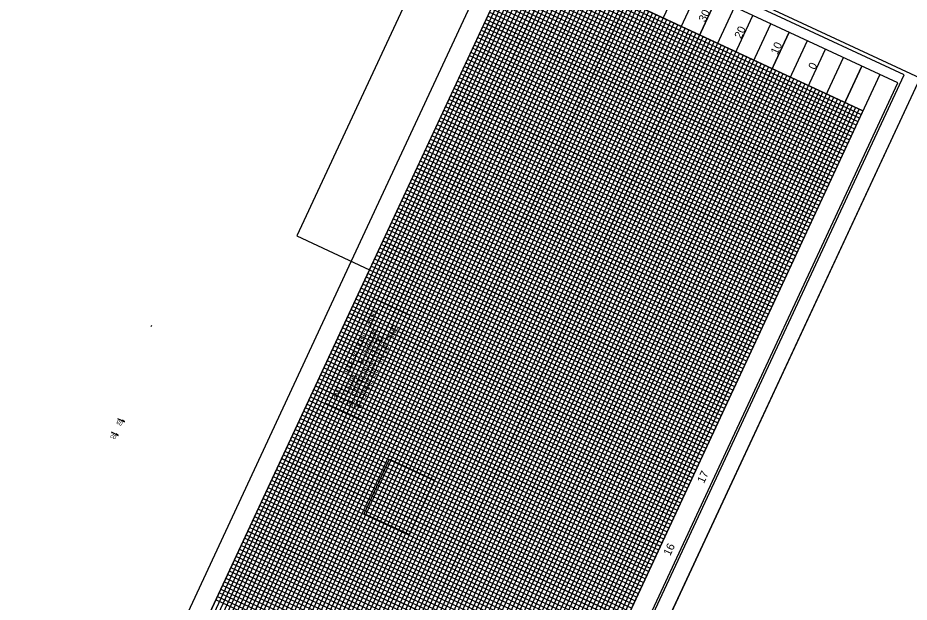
# Model space of a CAD drawing. Extents: x 2532214 to 2534758, y 714172 to 717266.
# Drawn here: x 2532790 to 2533904, y 715503 to 716233 of the extents above; entities that cross this region are included whole.
import ezdxf

# ---------------------------------------------------------------- set-up
doc = ezdxf.new("R2010")
doc.units = 0
for name, color, linetype in [('Arrowhead Terminators', 7, 'Continuous'), ('Default', 7, 'Continuous'), ('Dimension Lines', 7, 'Continuous'), ('Dimension Lines CELL', 7, 'Continuous'), ('Enter Data Field Text', 7, 'Continuous'), ('Mis Existing Structures', 7, 'Continuous'), ('Mis Ground Lines', 7, 'Continuous'), ('Plan Sheet', 7, 'Continuous'), ('Rebar Hooks Both Ends', 7, 'Continuous'), ('Rebar Lines', 7, 'Continuous'), ('Rebar with Hook on Left End', 7, 'Continuous'), ('Structural Steel Angle 3 x 3', 7, 'Continuous'), ('Structural Steel Channel 12', 7, 'Continuous'), ('Structural Steel Lines', 7, 'Continuous'), ('Subtitle Text', 7, 'Continuous'), ('Sup Concrete Girder Lines', 7, 'Continuous')]:
    doc.layers.add(name, color=color, linetype=linetype)

msp = doc.modelspace()

# ---------------------------------------------------------------- linework, layer by layer
at = {"layer": 'Arrowhead Terminators'}
msp.add_line((2533206.9, 714631.3), (2533917.1, 716157.7), dxfattribs=at)
at = {"layer": 'Default'}
for points in [[(2533174.3, 715751.9), (2533235, 715882.3), (2533280.2, 715861.3), (2533219.5, 715730.8)], [(2533174.3, 715751.9), (2533235, 715882.3), (2533280.2, 715861.3), (2533219.5, 715730.8)], [(2533223, 715613.7), (2533254.6, 715681.7), (2533310.6, 715655.7), (2533279, 715587.7)], [(2533223, 715613.7), (2533254.6, 715681.7), (2533310.6, 715655.7), (2533279, 715587.7)]]:
    msp.add_lwpolyline(points, close=True, dxfattribs=at)
at = {"layer": 'Dimension Lines'}
for p, q in [((2532826.1, 714992.1), (2533458.9, 716352.2)), ((2533504.2, 716331.1), (2532871.4, 714971.1)), ((2532916.8, 714950), (2533549.5, 716310)), ((2533404.5, 716294.7), (2533835.2, 716094.3)), ((2533594.9, 716288.9), (2532962.1, 714928.9)), ((2533007.4, 714907.8), (2533640.2, 716267.8)), ((2533814.1, 716049), (2533383.5, 716249.4)), ((2533685.5, 716246.7), (2533052.8, 714886.7)), ((2533098.1, 714865.6), (2533730.9, 716225.6)), ((2533776.2, 716204.5), (2533143.4, 714844.5)), ((2533362.4, 716204), (2533793, 716003.7)), ((2533188.8, 714823.4), (2533821.5, 716183.4)), ((2533771.9, 715958.3), (2533341.3, 716158.7)), ((2533320.2, 716113.4), (2533750.9, 715913)), ((2533729.8, 715867.7), (2533299.1, 716068)), ((2533278, 716022.7), (2533708.7, 715822.3)), ((2533687.6, 715777), (2533256.9, 715977.4)), ((2533235.8, 715932), (2533666.5, 715731.7)), ((2533645.4, 715686.3), (2533214.7, 715886.7)), ((2533193.6, 715841.4), (2533624.3, 715641)), ((2533603.2, 715595.7), (2533172.5, 715796)), ((2533151.5, 715750.7), (2533582.1, 715550.3)), ((2533561, 715505), (2533130.4, 715705.4)), ((2533109.3, 715660), (2533539.9, 715459.7)), ((2533518.8, 715414.3), (2533088.2, 715614.7)), ((2533067.1, 715569.4), (2533497.8, 715369)), ((2533476.7, 715323.7), (2533046, 715524))]:
    msp.add_line(p, q, dxfattribs=at)
at = {"layer": 'Dimension Lines CELL'}
msp.add_lwpolyline([(2533392.4, 716327.9), (2533206.8, 715929), (2532801.9, 715058.6), (2532325.9, 715280), (2532853.1, 716413.3), (2533042.4, 716325.3), (2533105.7, 716461.3), (2533324.4, 716359.6)], close=True, dxfattribs=at)
at = {"layer": 'Enter Data Field Text'}
msp.add_line((2532957.3, 715848.8), (2532956.5, 715847.2), dxfattribs=at)
for points in [[(2532923.4, 715728.3), (2532921.2, 715730.5), (2532921.3, 715729.3)], [(2532915.5, 715711.4), (2532913.3, 715713.6), (2532913.5, 715712.4)]]:
    msp.add_lwpolyline(points, close=True, dxfattribs=at)
at = {"layer": 'Mis Existing Structures'}
msp.add_lwpolyline([(2533194.3, 714651.5), (2533897.1, 716162.1), (2532940.5, 716607.1), (2532237.8, 715096.6)], close=True, dxfattribs=at)
at = {"layer": 'Mis Ground Lines'}
msp.add_lwpolyline([(2533206.9, 714631.3), (2533917.1, 716157.7), (2532924.3, 716619.6), (2532214.1, 715093.2)], close=True, dxfattribs=at)
at = {"layer": 'Plan Sheet'}
for p, q in [((2532848.8, 714981.6), (2533460.4, 716296.3)), ((2532939.4, 714939.4), (2533572.2, 716299.4)), ((2532894.1, 714960.5), (2533505.8, 716275.2)), ((2532984.8, 714918.3), (2533617.5, 716278.3)), ((2533394, 716272), (2533824.7, 716071.7)), ((2533030.1, 714897.2), (2533662.9, 716257.2)), ((2533075.4, 714876.1), (2533708.2, 716236.2)), ((2533372.9, 716226.7), (2533803.6, 716026.3)), ((2533120.8, 714855), (2533753.5, 716215.1)), ((2533166.1, 714834), (2533798.9, 716194)), ((2533351.8, 716181.4), (2533782.5, 715981)), ((2533211.4, 714812.9), (2533844.2, 716172.9)), ((2533330.7, 716136), (2533761.4, 715935.7)), ((2533309.6, 716090.7), (2533740.3, 715890.3)), ((2533288.5, 716045.4), (2533719.2, 715845)), ((2533267.5, 716000), (2533698.1, 715799.7)), ((2533246.4, 715954.7), (2533677, 715754.3)), ((2533225.3, 715909.4), (2533655.9, 715709)), ((2533204.2, 715864), (2533634.8, 715663.7)), ((2533183.1, 715818.7), (2533613.8, 715618.3)), ((2533162, 715773.4), (2533592.7, 715573)), ((2533140.9, 715728), (2533571.6, 715527.7)), ((2533119.8, 715682.7), (2533550.5, 715482.3)), ((2533098.7, 715637.4), (2533529.4, 715437)), ((2533077.6, 715592), (2533508.3, 715391.7)), ((2533056.5, 715546.7), (2533487.2, 715346.3))]:
    msp.add_line(p, q, dxfattribs=at)
at = {"layer": 'Rebar Lines'}
for p, q in [((2533419.6, 716315.3), (2532829.1, 715045.9)), ((2532833.6, 715043.8), (2533424.2, 716313.2)), ((2533428.7, 716311), (2532838.1, 715041.7)), ((2532842.7, 715039.6), (2533433.2, 716308.9)), ((2533442.3, 716304.7), (2532851.7, 715035.4)), ((2533408.8, 716303.8), (2533839.4, 716103.4)), ((2533841.5, 716107.9), (2533410.9, 716308.3)), ((2533413, 716312.8), (2533843.7, 716112.5)), ((2532856.3, 715033.3), (2533446.8, 716302.6)), ((2533451.4, 716300.5), (2532860.8, 715031.1)), ((2532865.3, 715029), (2533455.9, 716298.4)), ((2533465, 716294.2), (2532874.4, 715024.8)), ((2533837.3, 716098.9), (2533406.7, 716299.2)), ((2532878.9, 715022.7), (2533469.5, 716292.1)), ((2533474, 716289.9), (2532883.5, 715020.6)), ((2532888, 715018.5), (2533478.6, 716287.8)), ((2533487.6, 716283.6), (2532897.1, 715014.3)), ((2532901.6, 715012.2), (2533492.2, 716281.5)), ((2533831, 716085.3), (2533400.3, 716285.6)), ((2533402.4, 716290.2), (2533833.1, 716089.8)), ((2533496.7, 716279.4), (2532906.1, 715010.1)), ((2532910.7, 715007.9), (2533501.2, 716277.3)), ((2532919.7, 715003.7), (2533510.3, 716273.1)), ((2533514.8, 716271), (2532924.3, 715001.6)), ((2533826.8, 716076.2), (2533396.1, 716276.6)), ((2533398.2, 716281.1), (2533828.9, 716080.7)), ((2532928.8, 714999.5), (2533519.4, 716268.9)), ((2533523.9, 716266.7), (2532933.3, 714997.4)), ((2532942.4, 714993.2), (2533533, 716262.5)), ((2533537.5, 716260.4), (2532946.9, 714991.1)), ((2533820.5, 716062.6), (2533389.8, 716263)), ((2533391.9, 716267.5), (2533822.6, 716067.1)), ((2532951.5, 714989), (2533542, 716258.3)), ((2533546.6, 716256.2), (2532956, 714986.9)), ((2532965.1, 714982.6), (2533555.6, 716252)), ((2533560.2, 716249.9), (2532969.6, 714980.5)), ((2533816.2, 716053.5), (2533385.6, 716253.9)), ((2533387.7, 716258.4), (2533818.3, 716058.1)), ((2532974.1, 714978.4), (2533564.7, 716247.8)), ((2533569.2, 716245.7), (2532978.7, 714976.3)), ((2532987.7, 714972.1), (2533578.3, 716241.4)), ((2533582.8, 716239.3), (2532992.3, 714970)), ((2532996.8, 714967.9), (2533587.4, 716237.2)), ((2533809.9, 716039.9), (2533379.2, 716240.3)), ((2533381.3, 716244.8), (2533812, 716044.5)), ((2533591.9, 716235.1), (2533001.3, 714965.8)), ((2533010.4, 714961.5), (2533601, 716230.9)), ((2533605.5, 716228.8), (2533014.9, 714959.4)), ((2533019.5, 714957.3), (2533610, 716226.7)), ((2533805.7, 716030.9), (2533375, 716231.2)), ((2533377.1, 716235.8), (2533807.8, 716035.4)), ((2533614.6, 716224.6), (2533024, 714955.2)), ((2533033.1, 714951), (2533623.6, 716220.3)), ((2533628.2, 716218.2), (2533037.6, 714948.9)), ((2533042.1, 714946.8), (2533632.7, 716216.1)), ((2533799.4, 716017.3), (2533368.7, 716217.6)), ((2533370.8, 716222.2), (2533801.5, 716021.8)), ((2533637.2, 716214), (2533046.7, 714944.7)), ((2533055.7, 714940.5), (2533646.3, 716209.8)), ((2533650.8, 716207.7), (2533060.3, 714938.3)), ((2533064.8, 714936.2), (2533655.4, 716205.6)), ((2533659.9, 716203.5), (2533069.3, 714934.1)), ((2533795.1, 716008.2), (2533364.5, 716208.6)), ((2533366.6, 716213.1), (2533797.3, 716012.7)), ((2533078.4, 714929.9), (2533669, 716199.3)), ((2533673.5, 716197.1), (2533082.9, 714927.8)), ((2533087.5, 714925.7), (2533678, 716195)), ((2533682.6, 716192.9), (2533092, 714923.6)), ((2533788.8, 715994.6), (2533358.1, 716195)), ((2533360.3, 716199.5), (2533790.9, 715999.1)), ((2533101.1, 714919.4), (2533691.6, 716188.7)), ((2533696.2, 716186.6), (2533105.6, 714917.3)), ((2533110.1, 714915.1), (2533700.7, 716184.5)), ((2533705.2, 716182.4), (2533114.7, 714913)), ((2533784.6, 715985.5), (2533353.9, 716185.9)), ((2533356, 716190.4), (2533786.7, 715990.1)), ((2533123.7, 714908.8), (2533714.3, 716178.2)), ((2533718.8, 716176.1), (2533128.3, 714906.7)), ((2533132.8, 714904.6), (2533723.4, 716173.9)), ((2533727.9, 716171.8), (2533137.3, 714902.5)), ((2533778.3, 715971.9), (2533347.6, 716172.3)), ((2533349.7, 716176.8), (2533780.4, 715976.5)), ((2533146.4, 714898.3), (2533737, 716167.6)), ((2533741.5, 716165.5), (2533150.9, 714896.2)), ((2533155.5, 714894.1), (2533746, 716163.4)), ((2533750.6, 716161.3), (2533160, 714891.9)), ((2533774.1, 715962.9), (2533343.4, 716163.2)), ((2533345.5, 716167.8), (2533776.2, 715967.4)), ((2533169.1, 714887.7), (2533759.6, 716157.1)), ((2533764.2, 716155), (2533173.6, 714885.6)), ((2533178.1, 714883.5), (2533768.7, 716152.9)), ((2533773.2, 716150.7), (2533182.7, 714881.4)), ((2533767.7, 715949.3), (2533337.1, 716149.6)), ((2533339.2, 716154.2), (2533769.8, 715953.8)), ((2533191.7, 714877.2), (2533782.3, 716146.5)), ((2533196.3, 714875.1), (2533786.8, 716144.4)), ((2533791.4, 716142.3), (2533200.8, 714873)), ((2533205.3, 714870.9), (2533795.9, 716140.2)), ((2533763.5, 715940.2), (2533332.8, 716140.6)), ((2533334.9, 716145.1), (2533765.6, 715944.7)), ((2533805, 716136), (2533214.4, 714866.6)), ((2533218.9, 714864.5), (2533809.5, 716133.9)), ((2533814, 716131.8), (2533223.5, 714862.4)), ((2533228, 714860.3), (2533818.6, 716129.7)), ((2533757.2, 715926.6), (2533326.5, 716127)), ((2533328.6, 716131.5), (2533759.3, 715931.1)), ((2533827.6, 716125.4), (2533237.1, 714856.1)), ((2533241.6, 714854), (2533832.2, 716123.3)), ((2533836.7, 716121.2), (2533246.1, 714851.9)), ((2533250.7, 714849.8), (2533841.2, 716119.1)), ((2533753, 715917.5), (2533322.3, 716117.9)), ((2533324.4, 716122.4), (2533755.1, 715922.1)), ((2533746.6, 715903.9), (2533316, 716104.3)), ((2533318.1, 716108.8), (2533748.7, 715908.5)), ((2533742.4, 715894.9), (2533311.7, 716095.2)), ((2533313.9, 716099.8), (2533744.5, 715899.4)), ((2533736.1, 715881.3), (2533305.4, 716081.6)), ((2533307.5, 716086.2), (2533738.2, 715885.8)), ((2533731.9, 715872.2), (2533301.2, 716072.6)), ((2533303.3, 716077.1), (2533734, 715876.7)), ((2533725.5, 715858.6), (2533294.9, 716059)), ((2533297, 716063.5), (2533727.7, 715863.1)), ((2533721.3, 715849.5), (2533290.7, 716049.9)), ((2533292.8, 716054.4), (2533723.4, 715854.1)), ((2533286.4, 716040.8), (2533717.1, 715840.5)), ((2533710.8, 715826.9), (2533280.1, 716027.2)), ((2533282.2, 716031.8), (2533712.9, 715831.4)), ((2533715, 715835.9), (2533284.3, 716036.3)), ((2533275.9, 716018.2), (2533706.6, 715817.8)), ((2533700.2, 715804.2), (2533269.6, 716004.6)), ((2533271.7, 716009.1), (2533702.3, 715808.7)), ((2533704.5, 715813.3), (2533273.8, 716013.6)), ((2533265.3, 715995.5), (2533696, 715795.1)), ((2533689.7, 715781.5), (2533259, 715981.9)), ((2533261.1, 715986.4), (2533691.8, 715786.1)), ((2533693.9, 715790.6), (2533263.2, 715991)), ((2533254.8, 715972.8), (2533685.5, 715772.5)), ((2533679.1, 715758.9), (2533248.5, 715959.2)), ((2533250.6, 715963.8), (2533681.3, 715763.4)), ((2533683.4, 715767.9), (2533252.7, 715968.3)), ((2533244.3, 715950.2), (2533674.9, 715749.8)), ((2533668.6, 715736.2), (2533237.9, 715936.6)), ((2533240, 715941.1), (2533670.7, 715740.7)), ((2533672.8, 715745.3), (2533242.1, 715945.6)), ((2533233.7, 715927.5), (2533664.4, 715727.1)), ((2533229.5, 715918.4), (2533660.2, 715718.1)), ((2533662.3, 715722.6), (2533231.6, 715923)), ((2533223.2, 715904.8), (2533653.8, 715704.5)), ((2533658.1, 715713.5), (2533227.4, 715913.9)), ((2533218.9, 715895.8), (2533649.6, 715695.4)), ((2533651.7, 715699.9), (2533221.1, 715900.3)), ((2533212.6, 715882.2), (2533643.3, 715681.8)), ((2533647.5, 715690.9), (2533216.8, 715891.2)), ((2533208.4, 715873.1), (2533639.1, 715672.7)), ((2533641.2, 715677.3), (2533210.5, 715877.6)), ((2533202.1, 715859.5), (2533632.7, 715659.1)), ((2533637, 715668.2), (2533206.3, 715868.6)), ((2533197.9, 715850.4), (2533628.5, 715650.1)), ((2533630.6, 715654.6), (2533200, 715855)), ((2533191.5, 715836.8), (2533622.2, 715636.5)), ((2533626.4, 715645.5), (2533195.7, 715845.9)), ((2533187.3, 715827.8), (2533618, 715627.4)), ((2533620.1, 715631.9), (2533189.4, 715832.3)), ((2533181, 715814.2), (2533611.6, 715613.8)), ((2533615.9, 715622.9), (2533185.2, 715823.2)), ((2533176.8, 715805.1), (2533607.4, 715604.7)), ((2533609.5, 715609.3), (2533178.9, 715809.6)), ((2533605.3, 715600.2), (2533174.7, 715800.6)), ((2533166.2, 715782.4), (2533596.9, 715582.1)), ((2533599, 715586.6), (2533168.3, 715787)), ((2533170.4, 715791.5), (2533601.1, 715591.1)), ((2533594.8, 715577.5), (2533164.1, 715777.9)), ((2533155.7, 715759.8), (2533586.3, 715559.4)), ((2533588.4, 715563.9), (2533157.8, 715764.3)), ((2533159.9, 715768.8), (2533590.6, 715568.5)), ((2533584.2, 715554.9), (2533153.6, 715755.2)), ((2533145.1, 715737.1), (2533575.8, 715536.7)), ((2533577.9, 715541.3), (2533147.2, 715741.6)), ((2533149.3, 715746.2), (2533580, 715545.8)), ((2533573.7, 715532.2), (2533143, 715732.6)), ((2533134.6, 715714.4), (2533565.2, 715514.1)), ((2533567.4, 715518.6), (2533136.7, 715719)), ((2533138.8, 715723.5), (2533569.5, 715523.1)), ((2533563.1, 715509.5), (2533132.5, 715709.9)), ((2533124, 715691.8), (2533554.7, 715491.4)), ((2533556.8, 715495.9), (2533126.1, 715696.3)), ((2533128.2, 715700.8), (2533558.9, 715500.5)), ((2533552.6, 715486.9), (2533121.9, 715687.2)), ((2533113.5, 715669.1), (2533544.2, 715468.7)), ((2533546.3, 715473.3), (2533115.6, 715673.6)), ((2533117.7, 715678.2), (2533548.4, 715477.8)), ((2533542, 715464.2), (2533111.4, 715664.6)), ((2533535.7, 715450.6), (2533105, 715651)), ((2533107.2, 715655.5), (2533537.8, 715455.1)), ((2533531.5, 715441.5), (2533100.8, 715641.9)), ((2533102.9, 715646.4), (2533533.6, 715446.1)), ((2533525.2, 715427.9), (2533094.5, 715628.3)), ((2533096.6, 715632.8), (2533527.3, 715432.5)), ((2533521, 715418.9), (2533090.3, 715619.2)), ((2533092.4, 715623.8), (2533523.1, 715423.4)), ((2533514.6, 715405.3), (2533084, 715605.6)), ((2533086.1, 715610.2), (2533516.7, 715409.8)), ((2533510.4, 715396.2), (2533079.7, 715596.6)), ((2533081.8, 715601.1), (2533512.5, 715400.7)), ((2533504.1, 715382.6), (2533073.4, 715583)), ((2533075.5, 715587.5), (2533506.2, 715387.1)), ((2533499.9, 715373.5), (2533069.2, 715573.9)), ((2533071.3, 715578.4), (2533502, 715378.1)), ((2533493.5, 715359.9), (2533062.9, 715560.3)), ((2533065, 715564.8), (2533495.6, 715364.5)), ((2533489.3, 715350.9), (2533058.6, 715551.2)), ((2533060.8, 715555.8), (2533491.4, 715355.4)), ((2533483, 715337.3), (2533052.3, 715537.6)), ((2533054.4, 715542.2), (2533485.1, 715341.8)), ((2533478.8, 715328.2), (2533048.1, 715528.6)), ((2533050.2, 715533.1), (2533480.9, 715332.7)), ((2533472.4, 715314.6), (2533041.8, 715515)), ((2533043.9, 715519.5), (2533474.6, 715319.1)), ((2533468.2, 715305.5), (2533037.6, 715505.9)), ((2533039.7, 715510.4), (2533470.3, 715310.1))]:
    msp.add_line(p, q, dxfattribs=at)
at = {"layer": 'Structural Steel Angle 3 x 3'}
msp.add_lwpolyline([(2532325.9, 715280), (2532853.1, 716413.3), (2533042.4, 716325.3), (2533126.8, 716506.7), (2533345.5, 716404.9), (2533138.8, 715960.6), (2533229.5, 715918.4), (2532824.5, 715048)], close=True, dxfattribs=at)
at = {"layer": 'Structural Steel Channel 12'}
msp.add_lwpolyline([(2532824.5, 715048), (2533229.5, 715918.4), (2533415.1, 716317.4), (2533539.1, 716259.7), (2533845.8, 716117), (2533255.2, 714847.7)], close=True, dxfattribs=at)
at = {"layer": 'Structural Steel Lines'}
for p, q in [((2533436.2, 716362.7), (2532803.4, 715002.7)), ((2533866.9, 716162.3), (2533234.1, 714802.3))]:
    msp.add_line(p, q, dxfattribs=at)
msp.add_lwpolyline([(2532937.5, 716594.7), (2532304.8, 715234.7), (2533256.8, 714791.8), (2533889.5, 716151.8)], close=True, dxfattribs=at)
at = {"layer": 'Subtitle Text'}
for p, q in [((2532923.4, 715728.3), (2532915.1, 715732.3)), ((2532915.5, 715711.4), (2532907.2, 715715.4))]:
    msp.add_line(p, q, dxfattribs=at)
at = {"layer": 'Sup Concrete Girder Lines'}
for p, q in [((2533481.5, 716341.6), (2532848.8, 714981.6)), ((2532894.1, 714960.5), (2533526.9, 716320.5)), ((2533845.8, 716117), (2533415.1, 716317.4)), ((2533572.2, 716299.4), (2532939.4, 714939.4)), ((2532984.8, 714918.3), (2533617.5, 716278.3)), ((2533394, 716272), (2533824.7, 716071.7)), ((2533662.9, 716257.2), (2533030.1, 714897.2)), ((2533075.4, 714876.1), (2533708.2, 716236.2)), ((2533803.6, 716026.3), (2533372.9, 716226.7)), ((2533753.5, 716215.1), (2533120.8, 714855)), ((2533166.1, 714834), (2533798.9, 716194)), ((2533351.8, 716181.4), (2533782.5, 715981)), ((2533844.2, 716172.9), (2533211.4, 714812.9)), ((2533761.4, 715935.7), (2533330.7, 716136)), ((2533309.6, 716090.7), (2533740.3, 715890.3)), ((2533719.2, 715845), (2533288.5, 716045.4)), ((2533267.5, 716000), (2533698.1, 715799.7)), ((2533677, 715754.3), (2533246.4, 715954.7)), ((2533225.3, 715909.4), (2533655.9, 715709)), ((2533634.8, 715663.7), (2533204.2, 715864)), ((2533183.1, 715818.7), (2533613.8, 715618.3)), ((2533592.7, 715573), (2533162, 715773.4)), ((2533140.9, 715728), (2533571.6, 715527.7)), ((2533550.5, 715482.3), (2533119.8, 715682.7)), ((2533098.7, 715637.4), (2533529.4, 715437)), ((2533508.3, 715391.7), (2533077.6, 715592)), ((2533056.5, 715546.7), (2533487.2, 715346.3))]:
    msp.add_line(p, q, dxfattribs=at)

# ---------------------------------------------------------------- texts
at = {"layer": 'Default'}
for s, p in [('BM1       ELEVATION = 24.93', (2533188.1, 715754.3)), ('RR SPIKE SET IN 18" PINE', (2533216.6, 715741)), ('N 715991      E 2533024', (2533197.6, 715749.8)), ('BL STATION 32+22.00', (2533207.1, 715745.4))]:
    msp.add_text(s, height=7, rotation=65.05, dxfattribs=at).set_placement(p)
at = {"layer": 'Rebar Hooks Both Ends'}
for s, p in [('30', (2533648.9, 716227)), ('20', (2533693.7, 716206.2)), ('10', (2533739, 716186.4)), ('0', (2533786, 716167.6))]:
    msp.add_text(s, height=10, rotation=65.05, dxfattribs=at).set_placement(p)
at = {"layer": 'Rebar with Hook on Left End'}
for s, p in [('17', (2533647.2, 715650.8)), ('16', (2533605.1, 715560.3))]:
    msp.add_text(s, height=10, rotation=65.05, dxfattribs=at).set_placement(p)
at = {"layer": 'Subtitle Text'}
for s, p in [('03', (2532922, 715727.7)), ('02', (2532914.1, 715710.8))]:
    msp.add_text(s, height=5, rotation=154.3396, dxfattribs=at).set_placement(p)

doc.saveas('drawing.dxf')
